(* Logix 5000 project; controller ANG1E_AOI_sample_RSLogix_V31 vendor 1 type 14 code 108 rev 31.11; software revision 31.02; part 4 of 5 *)
(* tags used below, declared in another part *)
   Least_Significant_Word : INT;
   upper_resultX1000 : DINT;   // intermediate value

ADD_ON_INSTRUCTION AMCI_ANG1E_Program_Motor_Current   (* revision 1.1, vendor AMCI *)
// Revision note:
// Version 1.1 added the slot_axis number and the input parameters can now be tags or discrete values.
VAR_INPUT
   slot_axis_number : INT; {required}
   motor_current : INT;
END_VAR
VAR_IN_OUT
   AMCI_ANG1E_output_data : INT[10]; {required}
END_VAR
VAR
   command_data_block : INT[10];
        [1]   // Command Bits LSW
        [3]   // Lower Target Position
        [5]   // Lower Programmed Speed
        [0]   // Command Bits MSW
        [2]   // Upper Target Position
        [4]   // Upper Programmed Speed
   index : INT;
END_VAR

ROUTINE Logic   (* ladder *)
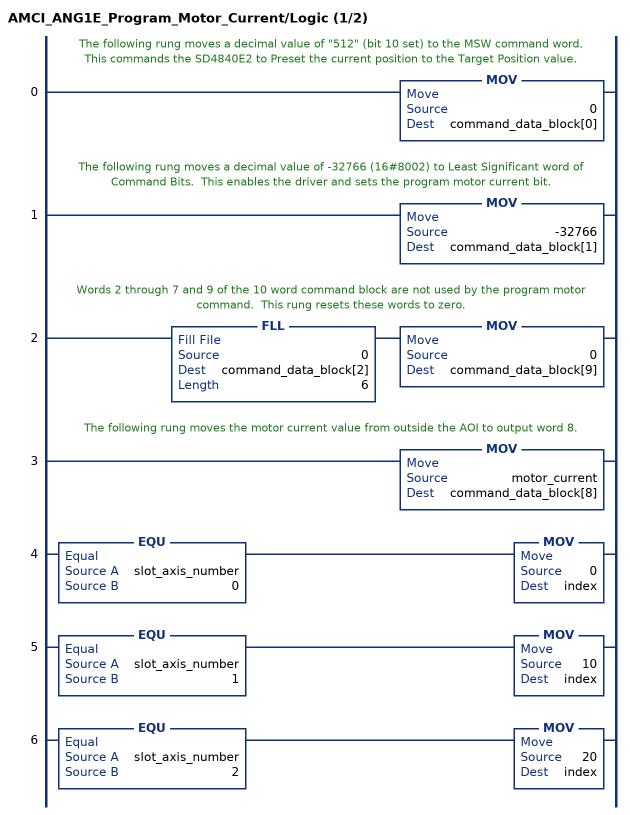
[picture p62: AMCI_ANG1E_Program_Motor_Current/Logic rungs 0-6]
   // The following rung moves a decimal value of "512" (bit 10 set) to the MSW command word.  This commands the SD4840E2 to Preset the current position to the Target Position value.
   0: MOV(0,command_data_block[0]);
   // The following rung moves a decimal value of -32766 (16#8002) to Least Significant word of Command Bits.  This enables the driver and sets the program motor current bit.
   1: MOV(-32766,command_data_block[1]);
   // Words 2 through 7 and 9 of the 10 word command block are not used by the program motor command.  This rung resets these words to zero.
   2: FLL(0,command_data_block[2],6)MOV(0,command_data_block[9]);
   // The following rung moves the motor current value from outside the AOI to output word 8.
   3: MOV(motor_current,command_data_block[8]);
   4: EQU(slot_axis_number,0)MOV(0,index);
   5: EQU(slot_axis_number,1)MOV(10,index);
   6: EQU(slot_axis_number,2)MOV(20,index);
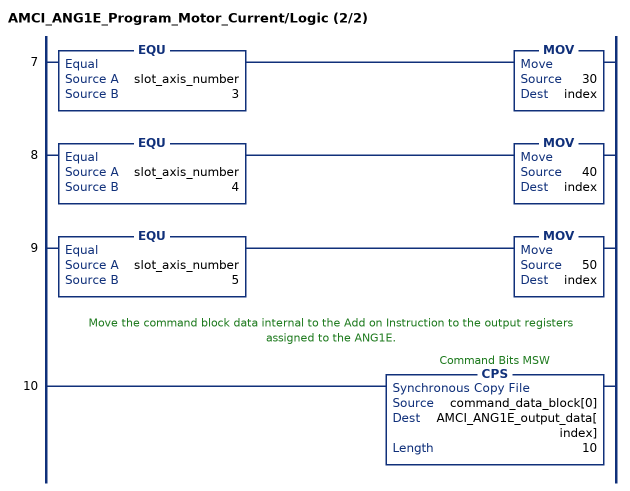
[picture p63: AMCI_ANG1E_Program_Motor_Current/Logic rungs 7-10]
   7: EQU(slot_axis_number,3)MOV(30,index);
   8: EQU(slot_axis_number,4)MOV(40,index);
   9: EQU(slot_axis_number,5)MOV(50,index);
   // Move the command block data internal to the Add on Instruction to the output registers assigned to the ANG1E.
   10: CPS(command_data_block[0],AMCI_ANG1E_output_data[index],10);
END_ROUTINE
END_ADD_ON_INSTRUCTION

ADD_ON_INSTRUCTION AMCI_ANG1E_Registration_Move_CCW   (* revision 5.0, vendor AMCI, ExecuteEnableInFalse *)
// Revision note:
// Version 5.0 unlatched the error bit if the rung goes false.
VAR_INPUT
   Type_0_for_standard_1_for_indexed : BOOL;
   Axis_Status_bits : INT; {required}
   slot_axis_number : INT; {required}
   Stopping_Distance : DINT; {required}
   Programmed_Speed : DINT; {required}
   Acceleration : INT; {required}
   Deceleration : INT; {required}
   Minimum_Registration_Move_Distance : DINT; {required}
END_VAR
VAR_IN_OUT
   AMCI_ANG1E_output_data : INT[10]; {required}
END_VAR
VAR_OUTPUT
   EN : BOOL; {access Read Only, visible}
   Registration_Move_CCW_Occurring : BOOL; {access Read Only, visible}
   ER : BOOL; {access Read Only, visible}
END_VAR
VAR
   Upper_Result_X_1000 : DINT;
   command_data_block : INT[10];
        [1]   // Command Bits LSW
        [3]   // Lower Target Position
        [5]   // Lower Programmed Speed
        [0]   // Command Bits MSW
        [2]   // Upper Target Position
        [4]   // Upper Programmed Speed
   index : INT;
END_VAR

ROUTINE EnableInFalse   (* ladder *)
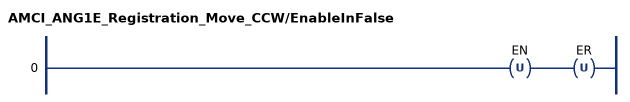
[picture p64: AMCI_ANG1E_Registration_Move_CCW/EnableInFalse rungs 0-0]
   0: OTU(EN)OTU(ER);
END_ROUTINE

ROUTINE Logic   (* ladder *)
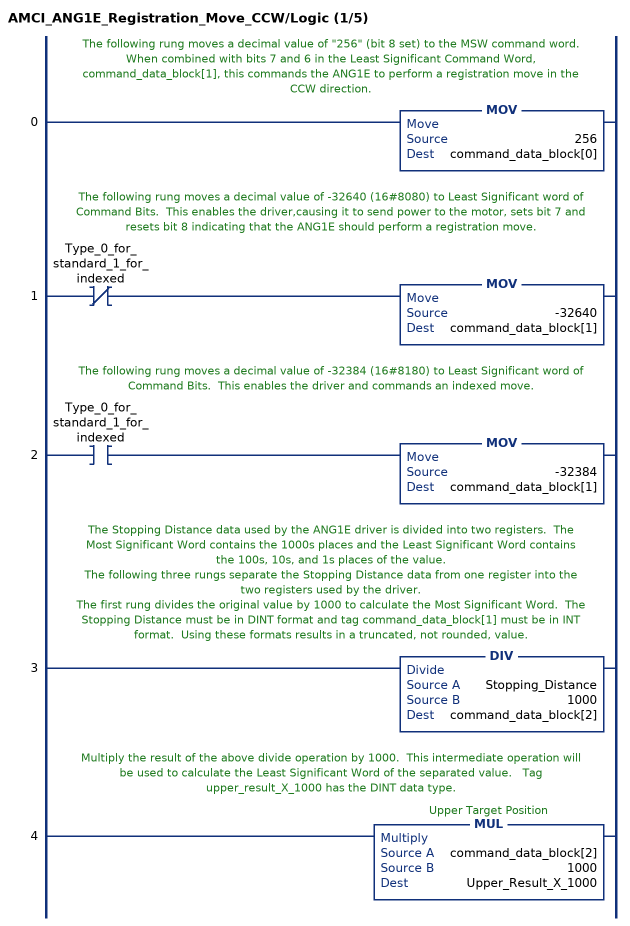
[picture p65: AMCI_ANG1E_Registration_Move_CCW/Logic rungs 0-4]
   // The following rung moves a decimal value of "256" (bit 8 set) to the MSW command word.  When combined with bits 7 and 6 in the Least Significant Command Word, command_data_block[1], this commands the ANG1E to perform a registration move in the CCW direction.
   0: MOV(256,command_data_block[0]);
   // The following rung moves a decimal value of -32640 (16#8080) to Least Significant word of Command Bits.  This enables the driver,causing it to send power to the motor, sets bit 7 and resets bit 8 indicating that the ANG1E should perform a registration move.
   1: XIO(Type_0_for_standard_1_for_indexed)MOV(-32640,command_data_block[1]);
   // The following rung moves a decimal value of -32384 (16#8180) to Least Significant word of Command Bits.  This enables the driver and commands an indexed move.
   2: XIC(Type_0_for_standard_1_for_indexed)MOV(-32384,command_data_block[1]);
   // The Stopping Distance data used by the ANG1E driver is divided into two registers.  The Most Significant Word contains the 1000s places and the Least Significant Word contains the 100s, 10s, and 1s places of the value.
   // The following three rungs separate the Stopping Distance data from one register into the two registers used by the driver.
   // The first rung divides the original value by 1000 to calculate the Most Significant Word.  The Stopping Distance must be in DINT format and tag command_data_block[1] must be in INT format.  Using these formats results in a truncated, not rounded, value.
   3: DIV(Stopping_Distance,1000,command_data_block[2]);
   // Multiply the result of the above divide operation by 1000.  This intermediate operation will be used to calculate the Least Significant Word of the separated value.   Tag upper_result_X_1000 has the DINT data type.
   4: MUL(command_data_block[2],1000,Upper_Result_X_1000);
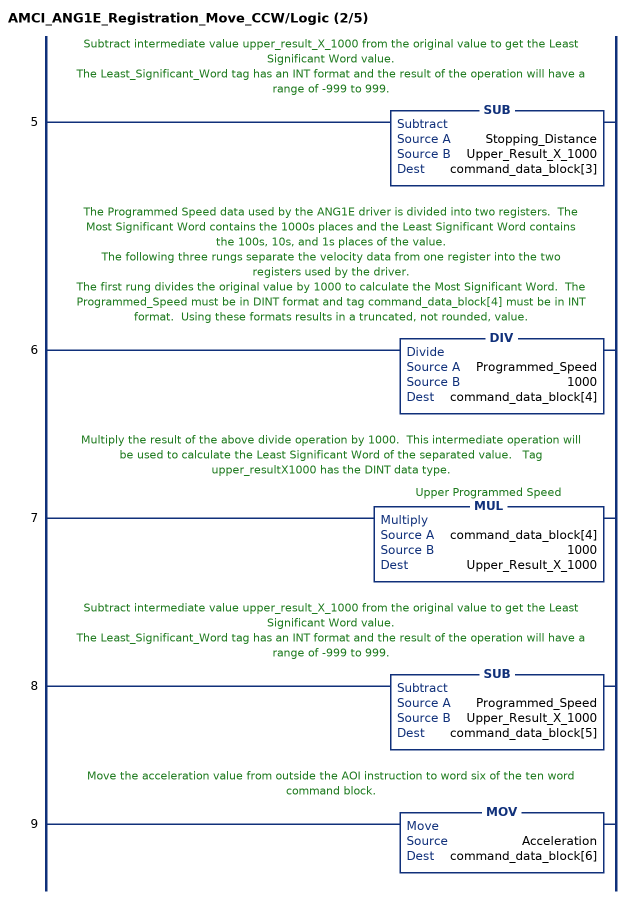
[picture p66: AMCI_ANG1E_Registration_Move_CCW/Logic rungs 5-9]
   // Subtract intermediate value upper_result_X_1000 from the original value to get the Least Significant Word value.
   // The Least_Significant_Word tag has an INT format and the result of the operation will have a range of -999 to 999.
   5: SUB(Stopping_Distance,Upper_Result_X_1000,command_data_block[3]);
   // The Programmed Speed data used by the ANG1E driver is divided into two registers.  The Most Significant Word contains the 1000s places and the Least Significant Word contains the 100s, 10s, and 1s places of the value.
   // The following three rungs separate the velocity data from one register into the two registers used by the driver.
   // The first rung divides the original value by 1000 to calculate the Most Significant Word.  The Programmed_Speed must be in DINT format and tag command_data_block[4] must be in INT format.  Using these formats results in a truncated, not rounded, value.
   6: DIV(Programmed_Speed,1000,command_data_block[4]);
   // Multiply the result of the above divide operation by 1000.  This intermediate operation will be used to calculate the Least Significant Word of the separated value.   Tag upper_resultX1000 has the DINT data type.
   7: MUL(command_data_block[4],1000,Upper_Result_X_1000);
   // Subtract intermediate value upper_result_X_1000 from the original value to get the Least Significant Word value.
   // The Least_Significant_Word tag has an INT format and the result of the operation will have a range of -999 to 999.
   8: SUB(Programmed_Speed,Upper_Result_X_1000,command_data_block[5]);
   // Move the acceleration value from outside the AOI instruction to word six of the ten word command block.
   9: MOV(Acceleration,command_data_block[6]);
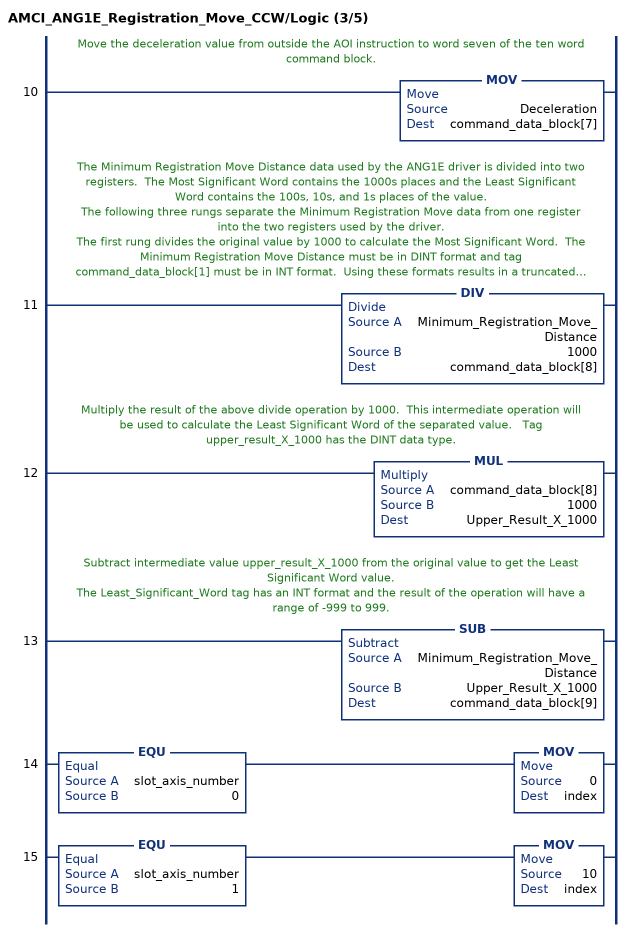
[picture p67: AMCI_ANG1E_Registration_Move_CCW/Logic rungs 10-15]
   // Move the deceleration value from outside the AOI instruction to word seven of the ten word command block.
   10: MOV(Deceleration,command_data_block[7]);
   // The Minimum Registration Move Distance data used by the ANG1E driver is divided into two registers.  The Most Significant Word contains the 1000s places and the Least Significant Word contains the 100s, 10s, and 1s places of the value.
   // The following three rungs separate the Minimum Registration Move data from one register into the two registers used by the driver.
   // The first rung divides the original value by 1000 to calculate the Most Significant Word.  The Minimum Registration Move Distance must be in DINT format and tag command_data_block[1] must be in INT format.  Using these formats results in a truncated, not rounded, value.
   11: DIV(Minimum_Registration_Move_Distance,1000,command_data_block[8]);
   // Multiply the result of the above divide operation by 1000.  This intermediate operation will be used to calculate the Least Significant Word of the separated value.   Tag upper_result_X_1000 has the DINT data type.
   12: MUL(command_data_block[8],1000,Upper_Result_X_1000);
   // Subtract intermediate value upper_result_X_1000 from the original value to get the Least Significant Word value.
   // The Least_Significant_Word tag has an INT format and the result of the operation will have a range of -999 to 999.
   13: SUB(Minimum_Registration_Move_Distance,Upper_Result_X_1000,command_data_block[9]);
   14: EQU(slot_axis_number,0)MOV(0,index);
   15: EQU(slot_axis_number,1)MOV(10,index);
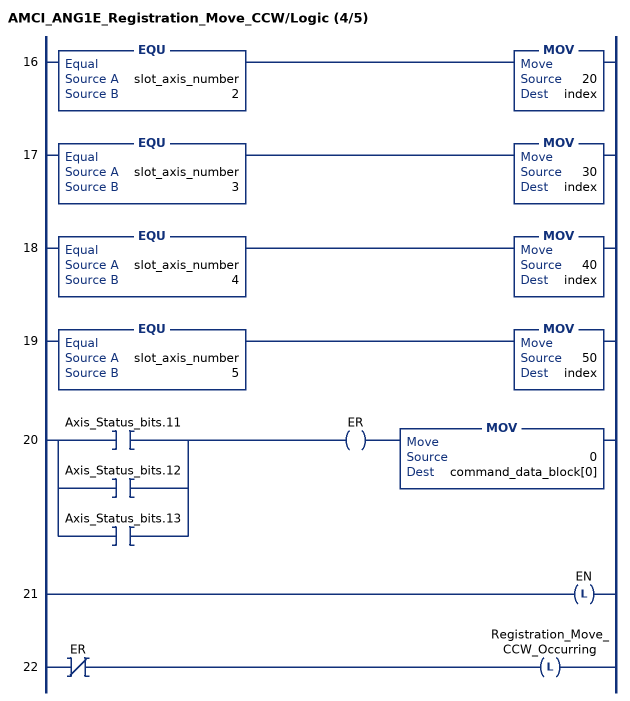
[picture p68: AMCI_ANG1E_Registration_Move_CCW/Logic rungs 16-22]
   16: EQU(slot_axis_number,2)MOV(20,index);
   17: EQU(slot_axis_number,3)MOV(30,index);
   18: EQU(slot_axis_number,4)MOV(40,index);
   19: EQU(slot_axis_number,5)MOV(50,index);
   20: [XIC(Axis_Status_bits.11) ,XIC(Axis_Status_bits.12) ,XIC(Axis_Status_bits.13) ]OTE(ER)MOV(0,command_data_block[0]);
   21: OTL(EN);
   22: XIO(ER)OTL(Registration_Move_CCW_Occurring);
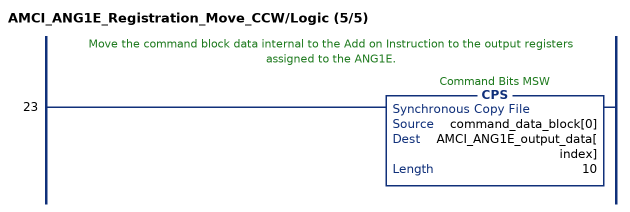
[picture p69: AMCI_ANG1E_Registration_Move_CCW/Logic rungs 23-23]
   // Move the command block data internal to the Add on Instruction to the output registers assigned to the ANG1E.
   23: CPS(command_data_block[0],AMCI_ANG1E_output_data[index],10);
END_ROUTINE
END_ADD_ON_INSTRUCTION

ADD_ON_INSTRUCTION AMCI_ANG1E_Registration_Move_CW   (* revision 5.0, vendor AMCI, ExecuteEnableInFalse *)
// Revision note:
// Version 5.0 unlatched the error bit if the rung goes false.
VAR_INPUT
   Axis_Status_Bits : INT; {required}
   slot_axis_number : INT; {required}
   type_0_for_standard_1_for_indexed : BOOL;
   Stopping_Distance : DINT; {required}
   Programmed_Speed : DINT; {required}
   Acceleration : INT; {required}
   Deceleration : INT; {required}
   Minimum_Registration_Move_Distance : DINT; {required}
END_VAR
VAR_IN_OUT
   AMCI_ANG1E_output_data : INT[10]; {required}
END_VAR
VAR_OUTPUT
   EN : BOOL; {access Read Only, visible}
   Registration_Move_CW_Occurring : BOOL; {access Read Only, visible}
   ER : BOOL; {access Read Only, visible}
END_VAR
VAR
   Upper_Result_X_1000 : DINT;
   command_data_block : INT[10];
        [1]   // Command Bits LSW
        [3]   // Lower Target Position
        [5]   // Lower Programmed Speed
        [0]   // Command Bits MSW
        [2]   // Upper Target Position
        [4]   // Upper Programmed Speed
   index : INT;
END_VAR

ROUTINE EnableInFalse   (* ladder *)
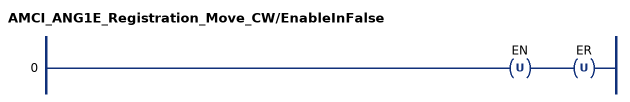
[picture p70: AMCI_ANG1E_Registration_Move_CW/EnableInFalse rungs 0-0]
   0: OTU(EN)OTU(ER);
END_ROUTINE

ROUTINE Logic   (* ladder *)
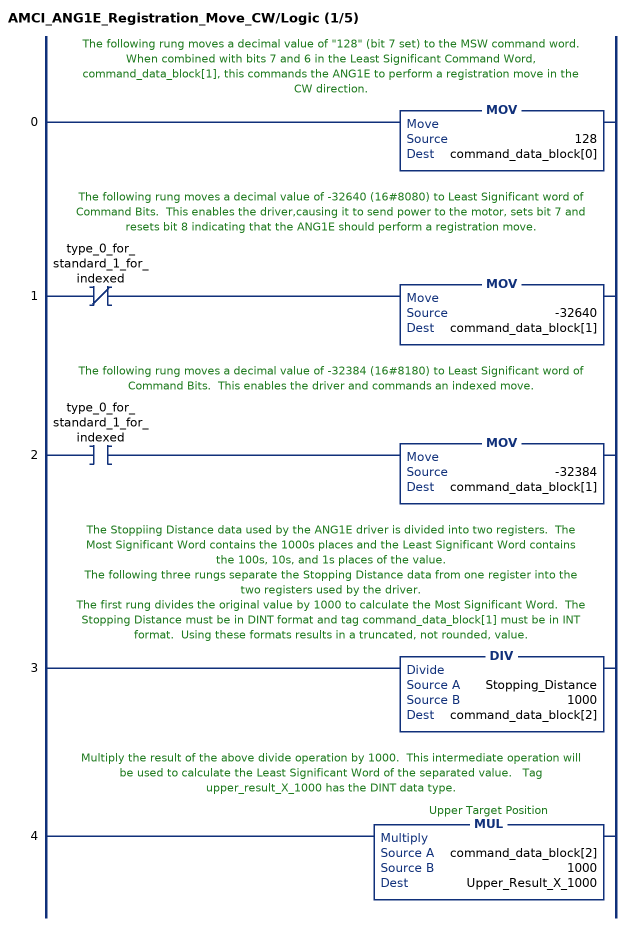
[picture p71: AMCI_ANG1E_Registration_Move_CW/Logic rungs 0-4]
   // The following rung moves a decimal value of "128" (bit 7 set) to the MSW command word.  When combined with bits 7 and 6 in the Least Significant Command Word, command_data_block[1], this commands the ANG1E to perform a registration move in the CW direction.
   0: MOV(128,command_data_block[0]);
   // The following rung moves a decimal value of -32640 (16#8080) to Least Significant word of Command Bits.  This enables the driver,causing it to send power to the motor, sets bit 7 and resets bit 8 indicating that the ANG1E should perform a registration move.
   1: XIO(type_0_for_standard_1_for_indexed)MOV(-32640,command_data_block[1]);
   // The following rung moves a decimal value of -32384 (16#8180) to Least Significant word of Command Bits.  This enables the driver and commands an indexed move.
   2: XIC(type_0_for_standard_1_for_indexed)MOV(-32384,command_data_block[1]);
   // The Stoppiing Distance data used by the ANG1E driver is divided into two registers.  The Most Significant Word contains the 1000s places and the Least Significant Word contains the 100s, 10s, and 1s places of the value.
   // The following three rungs separate the Stopping Distance data from one register into the two registers used by the driver.
   // The first rung divides the original value by 1000 to calculate the Most Significant Word.  The Stopping Distance must be in DINT format and tag command_data_block[1] must be in INT format.  Using these formats results in a truncated, not rounded, value.
   3: DIV(Stopping_Distance,1000,command_data_block[2]);
   // Multiply the result of the above divide operation by 1000.  This intermediate operation will be used to calculate the Least Significant Word of the separated value.   Tag upper_result_X_1000 has the DINT data type.
   4: MUL(command_data_block[2],1000,Upper_Result_X_1000);
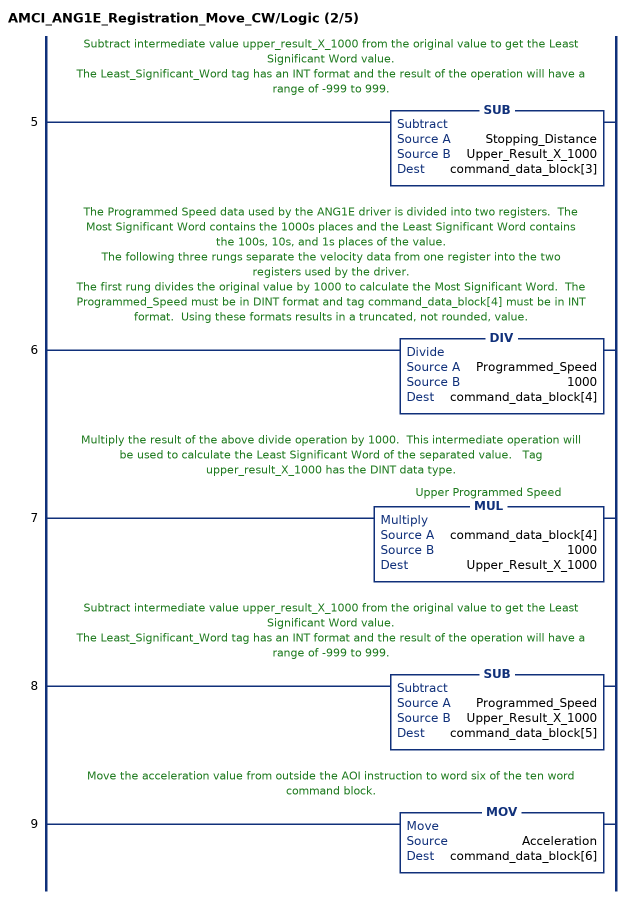
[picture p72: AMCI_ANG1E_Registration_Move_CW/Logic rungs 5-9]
   // Subtract intermediate value upper_result_X_1000 from the original value to get the Least Significant Word value.
   // The Least_Significant_Word tag has an INT format and the result of the operation will have a range of -999 to 999.
   5: SUB(Stopping_Distance,Upper_Result_X_1000,command_data_block[3]);
   // The Programmed Speed data used by the ANG1E driver is divided into two registers.  The Most Significant Word contains the 1000s places and the Least Significant Word contains the 100s, 10s, and 1s places of the value.
   // The following three rungs separate the velocity data from one register into the two registers used by the driver.
   // The first rung divides the original value by 1000 to calculate the Most Significant Word.  The Programmed_Speed must be in DINT format and tag command_data_block[4] must be in INT format.  Using these formats results in a truncated, not rounded, value.
   6: DIV(Programmed_Speed,1000,command_data_block[4]);
   // Multiply the result of the above divide operation by 1000.  This intermediate operation will be used to calculate the Least Significant Word of the separated value.   Tag upper_result_X_1000 has the DINT data type.
   7: MUL(command_data_block[4],1000,Upper_Result_X_1000);
   // Subtract intermediate value upper_result_X_1000 from the original value to get the Least Significant Word value.
   // The Least_Significant_Word tag has an INT format and the result of the operation will have a range of -999 to 999.
   8: SUB(Programmed_Speed,Upper_Result_X_1000,command_data_block[5]);
   // Move the acceleration value from outside the AOI instruction to word six of the ten word command block.
   9: MOV(Acceleration,command_data_block[6]);
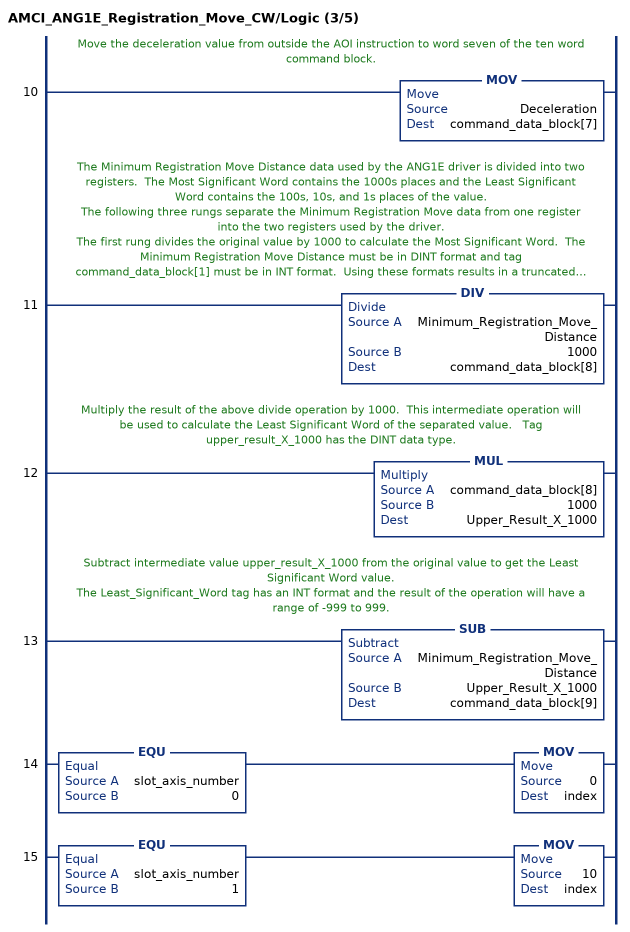
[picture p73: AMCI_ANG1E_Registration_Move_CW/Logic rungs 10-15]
   // Move the deceleration value from outside the AOI instruction to word seven of the ten word command block.
   10: MOV(Deceleration,command_data_block[7]);
   // The Minimum Registration Move Distance data used by the ANG1E driver is divided into two registers.  The Most Significant Word contains the 1000s places and the Least Significant Word contains the 100s, 10s, and 1s places of the value.
   // The following three rungs separate the Minimum Registration Move data from one register into the two registers used by the driver.
   // The first rung divides the original value by 1000 to calculate the Most Significant Word.  The Minimum Registration Move Distance must be in DINT format and tag command_data_block[1] must be in INT format.  Using these formats results in a truncated, not rounded, value.
   11: DIV(Minimum_Registration_Move_Distance,1000,command_data_block[8]);
   // Multiply the result of the above divide operation by 1000.  This intermediate operation will be used to calculate the Least Significant Word of the separated value.   Tag upper_result_X_1000 has the DINT data type.
   12: MUL(command_data_block[8],1000,Upper_Result_X_1000);
   // Subtract intermediate value upper_result_X_1000 from the original value to get the Least Significant Word value.
   // The Least_Significant_Word tag has an INT format and the result of the operation will have a range of -999 to 999.
   13: SUB(Minimum_Registration_Move_Distance,Upper_Result_X_1000,command_data_block[9]);
   14: EQU(slot_axis_number,0)MOV(0,index);
   15: EQU(slot_axis_number,1)MOV(10,index);
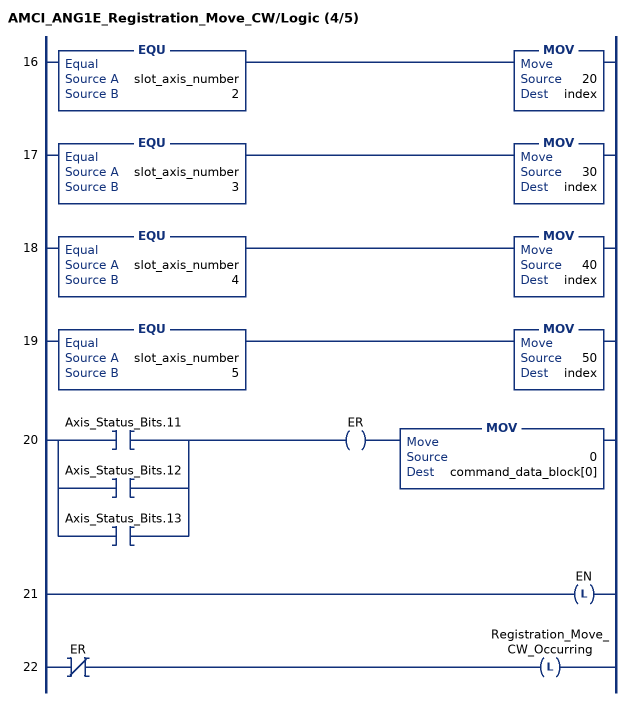
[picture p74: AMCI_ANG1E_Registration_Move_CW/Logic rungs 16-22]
   16: EQU(slot_axis_number,2)MOV(20,index);
   17: EQU(slot_axis_number,3)MOV(30,index);
   18: EQU(slot_axis_number,4)MOV(40,index);
   19: EQU(slot_axis_number,5)MOV(50,index);
   20: [XIC(Axis_Status_Bits.11) ,XIC(Axis_Status_Bits.12) ,XIC(Axis_Status_Bits.13) ]OTE(ER)MOV(0,command_data_block[0]);
   21: OTL(EN);
   22: XIO(ER)OTL(Registration_Move_CW_Occurring);
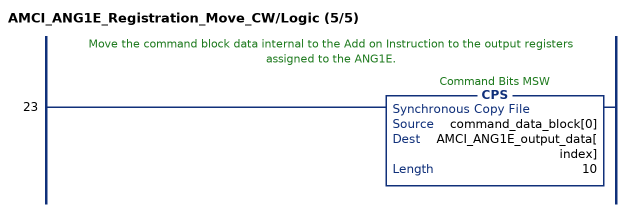
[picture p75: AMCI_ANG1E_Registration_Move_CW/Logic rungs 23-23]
   // Move the command block data internal to the Add on Instruction to the output registers assigned to the ANG1E.
   23: CPS(command_data_block[0],AMCI_ANG1E_output_data[index],10);
END_ROUTINE
END_ADD_ON_INSTRUCTION

ADD_ON_INSTRUCTION AMCI_ANG1E_Relative_Move   (* revision 6.1, vendor AMCI, ExecuteEnableInFalse *)
// Revision note:
// Version 5.0 added the (hidden) ability to program the motor current and unlatched the error bit if the rung goes false.
// 8/5/2019.  Version 6 automatically issued the reset error command if the move complete bit was set.  This will reset the move complete bit and allow short moves to occur.
// 7/31/23 V6.1 Changed how the AOI EN bit is set.   Instead of when the Move complete bit is not set, it is now set when the move command is issued.
VAR_INPUT
   Axis_Status_Bits : INT; {required}
   slot_axis_number : INT; {required}
   Type_0_for_standard_1_for_indexed : BOOL;
   Target_Position : DINT; {required}
   Programmed_Speed : DINT; {required}
   Acceleration : INT; {required}
   Deceleration : INT; {required}
   motor_current : INT;
   jerk : INT;
END_VAR
VAR_IN_OUT
   AMCI_ANG1E_output_data : INT[10]; {required}
END_VAR
VAR_OUTPUT
   EN : BOOL; {access Read Only, visible}
   ER : BOOL; {access Read Only, visible}
END_VAR
VAR
   Upper_Result_X_1000 : DINT;
   command_data_block : INT[10];
        [1]   // Command Bits LSW
        [3]   // Lower Target Position
        [5]   // Lower Programmed Speed
        [0]   // Command Bits MSW
        [2]   // Upper Target Position
        [4]   // Upper Programmed Speed
   index : INT;
END_VAR

ROUTINE EnableInFalse   (* ladder *)
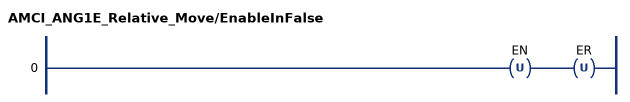
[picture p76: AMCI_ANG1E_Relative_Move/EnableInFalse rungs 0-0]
   0: OTU(EN)OTU(ER);
END_ROUTINE

ROUTINE Logic   (* ladder *)
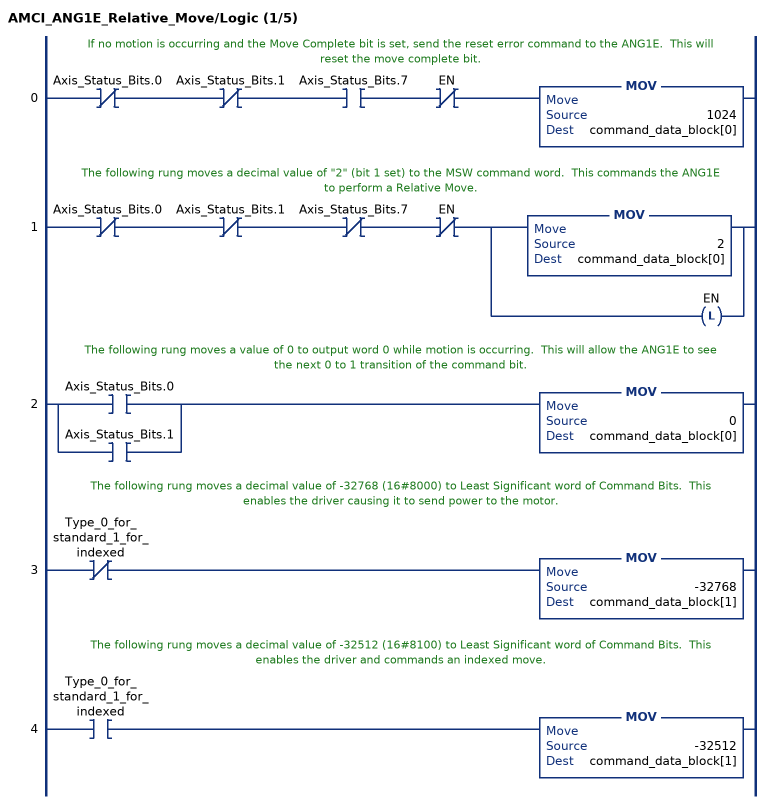
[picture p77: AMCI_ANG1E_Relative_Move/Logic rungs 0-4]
   // If no motion is occurring and the Move Complete bit is set, send the reset error command to the ANG1E.  This will reset the move complete bit.
   0: XIO(Axis_Status_Bits.0)XIO(Axis_Status_Bits.1)XIC(Axis_Status_Bits.7)XIO(EN)MOV(1024,command_data_block[0]);
   // The following rung moves a decimal value of "2" (bit 1 set) to the MSW command word.  This commands the ANG1E to perform a Relative Move.
   1: XIO(Axis_Status_Bits.0)XIO(Axis_Status_Bits.1)XIO(Axis_Status_Bits.7)XIO(EN)[MOV(2,command_data_block[0]) ,OTL(EN) ];
   // The following rung moves a value of 0 to output word 0 while motion is occurring.  This will allow the ANG1E to see the next 0 to 1 transition of the command bit.
   2: [XIC(Axis_Status_Bits.0) ,XIC(Axis_Status_Bits.1) ]MOV(0,command_data_block[0]);
   // The following rung moves a decimal value of -32768 (16#8000) to Least Significant word of Command Bits.  This enables the driver causing it to send power to the motor.
   3: XIO(Type_0_for_standard_1_for_indexed)MOV(-32768,command_data_block[1]);
   // The following rung moves a decimal value of -32512 (16#8100) to Least Significant word of Command Bits.  This enables the driver and commands an indexed move.
   4: XIC(Type_0_for_standard_1_for_indexed)MOV(-32512,command_data_block[1]);
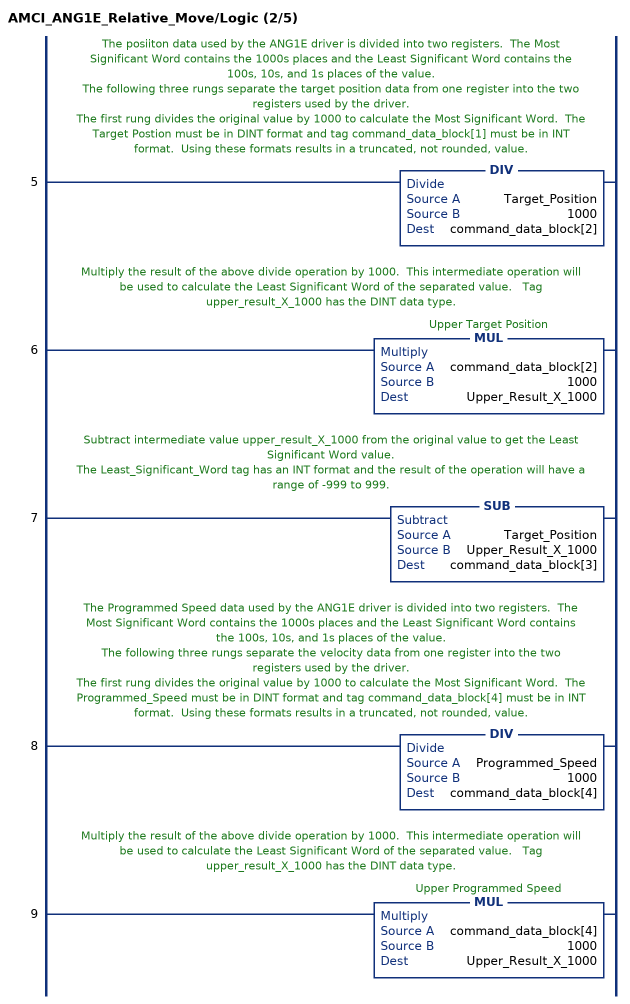
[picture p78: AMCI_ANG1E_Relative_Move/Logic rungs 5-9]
   // The posiiton data used by the ANG1E driver is divided into two registers.  The Most Significant Word contains the 1000s places and the Least Significant Word contains the 100s, 10s, and 1s places of the value.
   // The following three rungs separate the target position data from one register into the two registers used by the driver.
   // The first rung divides the original value by 1000 to calculate the Most Significant Word.  The Target Postion must be in DINT format and tag command_data_block[1] must be in INT format.  Using these formats results in a truncated, not rounded, value.
   5: DIV(Target_Position,1000,command_data_block[2]);
   // Multiply the result of the above divide operation by 1000.  This intermediate operation will be used to calculate the Least Significant Word of the separated value.   Tag upper_result_X_1000 has the DINT data type.
   6: MUL(command_data_block[2],1000,Upper_Result_X_1000);
   // Subtract intermediate value upper_result_X_1000 from the original value to get the Least Significant Word value.
   // The Least_Significant_Word tag has an INT format and the result of the operation will have a range of -999 to 999.
   7: SUB(Target_Position,Upper_Result_X_1000,command_data_block[3]);
   // The Programmed Speed data used by the ANG1E driver is divided into two registers.  The Most Significant Word contains the 1000s places and the Least Significant Word contains the 100s, 10s, and 1s places of the value.
   // The following three rungs separate the velocity data from one register into the two registers used by the driver.
   // The first rung divides the original value by 1000 to calculate the Most Significant Word.  The Programmed_Speed must be in DINT format and tag command_data_block[4] must be in INT format.  Using these formats results in a truncated, not rounded, value.
   8: DIV(Programmed_Speed,1000,command_data_block[4]);
   // Multiply the result of the above divide operation by 1000.  This intermediate operation will be used to calculate the Least Significant Word of the separated value.   Tag upper_result_X_1000 has the DINT data type.
   9: MUL(command_data_block[4],1000,Upper_Result_X_1000);
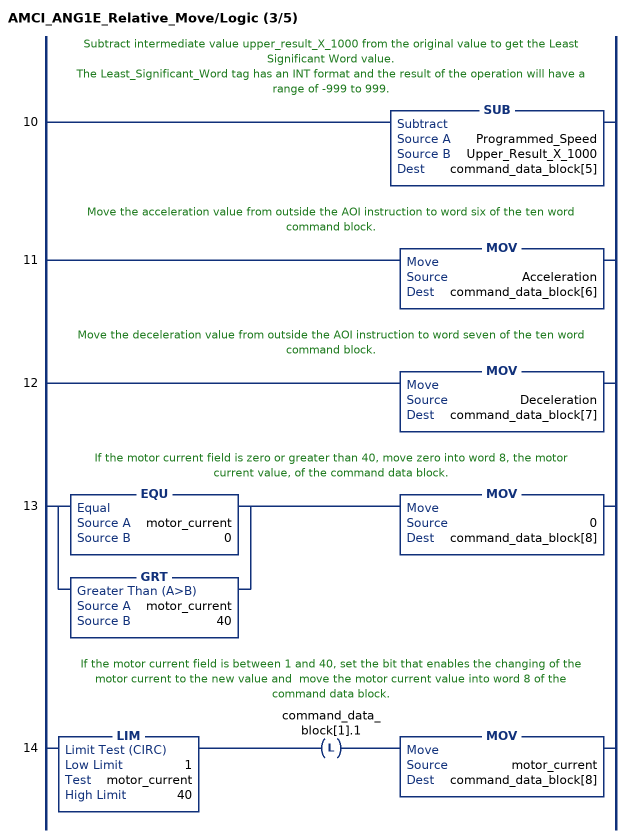
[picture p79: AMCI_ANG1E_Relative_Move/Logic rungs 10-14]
   // Subtract intermediate value upper_result_X_1000 from the original value to get the Least Significant Word value.
   // The Least_Significant_Word tag has an INT format and the result of the operation will have a range of -999 to 999.
   10: SUB(Programmed_Speed,Upper_Result_X_1000,command_data_block[5]);
   // Move the acceleration value from outside the AOI instruction to word six of the ten word command block.
   11: MOV(Acceleration,command_data_block[6]);
   // Move the deceleration value from outside the AOI instruction to word seven of the ten word command block.
   12: MOV(Deceleration,command_data_block[7]);
   // If the motor current field is zero or greater than 40, move zero into word 8, the motor current value, of the command data block.
   13: [EQU(motor_current,0) ,GRT(motor_current,40) ]MOV(0,command_data_block[8]);
   // If the motor current field is between 1 and 40, set the bit that enables the changing of the motor current to the new value and  move the motor current value into word 8 of the command data block.
   14: LIM(1,motor_current,40)OTL(command_data_block[1].1)MOV(motor_current,command_data_block[8]);
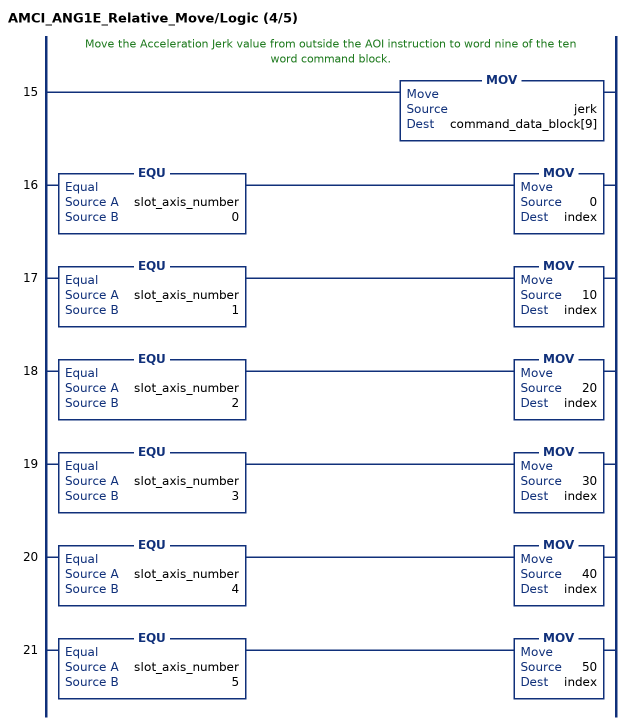
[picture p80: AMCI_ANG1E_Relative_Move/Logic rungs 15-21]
   // Move the Acceleration Jerk value from outside the AOI instruction to word nine of the ten word command block.
   15: MOV(jerk,command_data_block[9]);
   16: EQU(slot_axis_number,0)MOV(0,index);
   17: EQU(slot_axis_number,1)MOV(10,index);
   18: EQU(slot_axis_number,2)MOV(20,index);
   19: EQU(slot_axis_number,3)MOV(30,index);
   20: EQU(slot_axis_number,4)MOV(40,index);
   21: EQU(slot_axis_number,5)MOV(50,index);
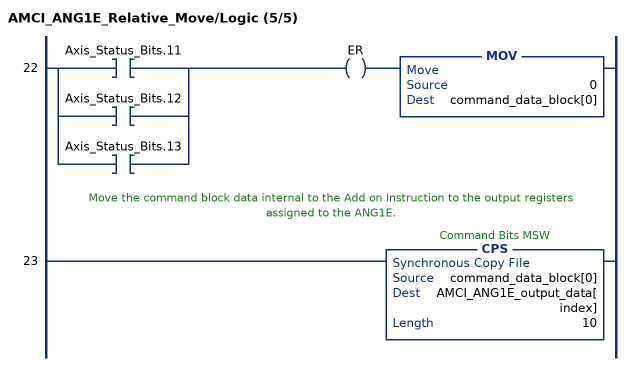
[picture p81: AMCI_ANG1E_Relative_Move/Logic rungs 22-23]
   22: [XIC(Axis_Status_Bits.11) ,XIC(Axis_Status_Bits.12) ,XIC(Axis_Status_Bits.13) ]OTE(ER)MOV(0,command_data_block[0]);
   // Move the command block data internal to the Add on Instruction to the output registers assigned to the ANG1E.
   23: CPS(command_data_block[0],AMCI_ANG1E_output_data[index],10);
END_ROUTINE
END_ADD_ON_INSTRUCTION
